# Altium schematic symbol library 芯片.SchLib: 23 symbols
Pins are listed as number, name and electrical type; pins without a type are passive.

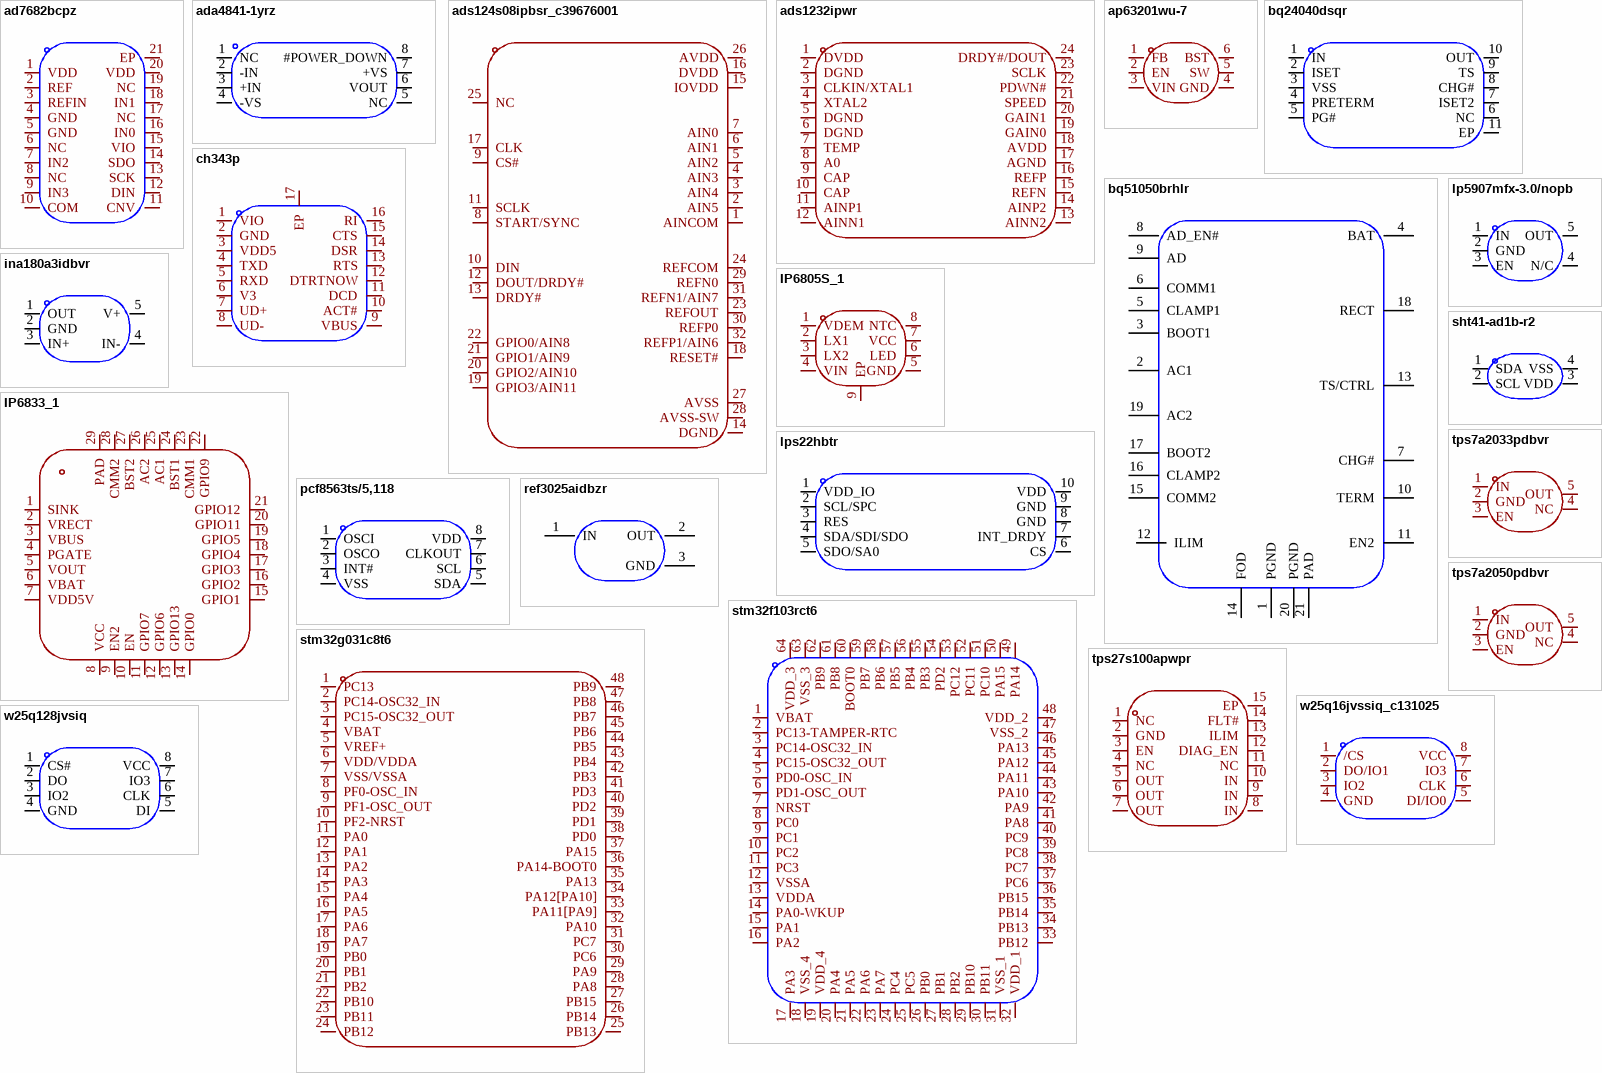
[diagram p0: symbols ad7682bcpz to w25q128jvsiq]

## ad7682bcpz
designator U??  (value not drawn)
分辨率(位):16;采样率:250kHz;工作电压:2.3V~5.5V;接口类型:SPI;; Manufacturer: ADI(亚德诺); AddInBom: yes; ModelId: a3340110063d416e8a07a046bfa25306; ModelName: LFCSP-20_L4.0-W4.0-H1.0-P0.50; ModelTransform: 157.48,157.48,0,90,0,0,-0.003,0.003,0; Resolution (Bits): 16; Sampling Rate: 250kHz; number of channels: 4; Interface: SPI; differential input: 是; Integral non - linearity: 0.4LSB; Signal-to-Noise Ratio: 92.5dB; Clock/Oscillator: 内置; ADC architecture: SAR; Quiescent Current (Iq): 50nA; DNL (LSB): 0.25LSB
footprint LFCSP-20_L4.0-W4.0-P0.50-BL-EP
pins: 1 VDD, 2 REF, 3 REFIN, 4 GND, 5 GND, 6 NC, 7 IN2, 8 NC, 9 IN3, 10 COM, 11 CNV, 12 DIN, 13 SCK, 14 SDO, 15 VIO, 16 IN0, 17 NC, 18 IN1, 19 NC, 20 VDD, 21 EP

## ada4841-1yrz
designator U??  (value not drawn)
放大器数:1;轨到轨:轨到轨输出;增益带宽积(GBW):80MHz;输入失调电压(Vos):300uV;压摆率(SR):12V/us;输入偏置电流(Ib):5.3uA;; Manufacturer: ADI(亚德诺); AddInBom: yes; ModelId: 7abc64c95a1a4a04a4ef38f9097c870b; ModelName: SOIC-8_L5.0-W4.0-P1.27-LS6.0-BL; ModelTransform: 192.913,236.22,0,0,0,0,0,0,0; Number of Channels: 1; Rail to Rail: 轨到轨输出; Gain Bandwidth Product: 80MHz; Vos - Input Offset Voltage: 300uV; Input Offset Voltage Drift(Vos TC): 1uV/℃; Slew Rate: 12V/us; Ib - Input Bias Current: 5.3uA; Input Offset Current(Ios): 500nA; Input Voltage Noise Density: 2.1nV/√Hz@100kHz; Common Mode Rejection Ratio(CMRR): 115dB; Quiescent Current: 1.5mA; Output Current: 30mA; Single supply: 2.7V~12V
footprint SOIC-8_L5.0-W4.0-P1.27-LS6.0-BL
pins: 1 NC, 2 -IN, 3 +IN, 4 -VS, 5 NC, 6 VOUT, 7 +VS, 8 #POWER_DOWN

## ads124s08ipbsr_c39676001
designator U??  (value not drawn)
分辨率(位):24;采样率:4kHz;工作电压:2.7V~5.25V;接口类型:SPI;; Manufacturer: TI(德州仪器); AddInBom: yes; ModelId: 0723864a05e7424ab80b3c78d6a7d93a; ModelName: TQFP-32_L5.0-W5.0-H1.2-LS7.0-P0.50; ModelTransform: 277.58783,277.58783,0,90,0,0,0.013,0,0; Resolution (Bits): 24; Sampling Rate: 4kHz; number of channels: 12; Interface: SPI; differential input: 是; Clock/Oscillator: 内置; Clock Frequency: 4.096MHz; Programmable Gain: 支持; Quiescent Current (Iq): 280uA
footprint TQFP-32_L5.0-W5.0-P0.50-LS7.0-BL
pins: 1 AINCOM, 2 AIN5, 3 AIN4, 4 AIN3, 5 AIN2, 6 AIN1, 7 AIN0, 8 START/SYNC, 9 CS#, 10 DIN, 11 SCLK, 12 DOUT/DRDY#, 13 DRDY#, 14 DGND, 15 IOVDD, 16 DVDD, 17 CLK, 18 RESET#, 19 GPIO3/AIN11, 20 GPIO2/AIN10, 21 GPIO1/AIN9, 22 GPIO0/AIN8, 23 REFOUT, 24 REFCOM, 25 NC, 26 AVDD, 27 AVSS, 28 AVSS-SW, 29 REFN0, 30 REFP0, 31 REFN1/AIN7, 32 REFP1/AIN6

## ads1232ipwr
designator U??  (value not drawn)
分辨率(位):24;采样率:10Hz;工作电压:2.7V~5.3V;接口类型:SPI;; Manufacturer: TI(德州仪器); AddInBom: yes; ModelId: 57e278220af748a2882c4abba4094eb9; ModelName: TSSOP-24_L7.8-W4.4-H1.0-LS6.4-P0.65; ModelTransform: 252.188,307.086,0,90,0,0,0,0,0; Resolution (Bits): 24; Sampling Rate: 10Hz; number of channels: 2; Interface: SPI; differential input: 是; Clock/Oscillator: 内置；外置; Clock Frequency: 4.9152MHz；200kHz~8MHz; Voltage Reference: 外置; Programmable Gain: 支持; Temperature Sensors: 内置; ADC architecture: Sigma-Delta; Data rate: 80Hz；10Hz; Quiescent Current (Iq): 1.3uA; Full-Scale Range(FSR): 39mV；1.25V；19.5mV；2.5V
footprint TSSOP-24_L7.8-W4.4-P0.65-LS6.4-BL
footprint Model Name (Footprint not found)
pins: 1 DVDD, 2 DGND, 3 CLKIN/XTAL1, 4 XTAL2, 5 DGND, 6 DGND, 7 TEMP, 8 A0, 9 CAP, 10 CAP, 11 AINP1, 12 AINN1, 13 AINN2, 14 AINP2, 15 REFN, 16 REFP, 17 AGND, 18 AVDD, 19 GAIN0, 20 GAIN1, 21 SPEED, 22 PDWN#, 23 SCLK, 24 DRDY#/DOUT

## ap63201wu-7
designator U??  (value not drawn)
功能类型:降压型;工作电压:3.8V~32V;输出电压:-;输出电流:2A;输出类型:可调;; Manufacturer: DIODES(美台); AddInBom: yes; ModelId: 2c4039b5b88644c1bda4b4ba9e971667; ModelName: TSOT-23-6_L2.9-W1.6-H1.1-LS2.8-P0.95; ModelTransform: 110.45568,114.173,0,180,0,0,-0.005,-0.0005,0; Function: 降压型; Output Current: 2A; Frequency - Switching: 500kHz; Synchronous Rectifier: 是; Number of Outputs: 1; Topology: 降压式; Quiescent Current: 22uA; Switch tube (built-in/external): 内置; Output Type: 可调
footprint TSOT-23-6_L2.9-W1.6-P0.95-LS2.8-BR
pins: 1 FB, 2 EN, 3 VIN, 4 GND, 5 SW, 6 BST

## bq24040dsqr
designator U??  (value not drawn)
工作电压:3.5V~28V;最大充电电流:1A;电池类型:锂电池;电池节数:1;; Manufacturer: TI(德州仪器); AddInBom: yes; ModelId: 0e1275d2e7d54e69a402a354e9203fe9; ModelName: WSON-10_L2.0-W2.0-H0.8-P0.40; ModelTransform: 78.74,79.527,0,0,0,0,0,0,0; The Chip Type: 充电芯片; Charge Current - Max: 1A; Charging Saturation Voltage: 4.2V; End-Off Voltage: 800mV; Type of Battery: 锂电池; Number of Cells: 1; Battery Temperature Detection: 支持; Supply Current (Iq): 1mA
footprint WSON-10_L2.0-W2.0-P0.40-BL-EP
pins: 1 IN, 2 ISET, 3 VSS, 4 PRETERM, 5 PG#, 6 NC, 7 ISET2, 8 CHG#, 9 TS, 10 OUT, 11 EP

## bq51050brhlr
designator U??  (value not drawn)
工作电压:4V~10V;最大充电电流:1.5A;电池类型:锂电池;电池节数:-;; Manufacturer: TI(德州仪器); AddInBom: yes; ModelId: 106b197ca8ab4e02bb62e74add4294be; ModelName: QFN-20_L4.5-W3.5-H1.0-P0.50; ModelTransform: 177.952,138.5824,0,0,0,0,0,0,0; The Chip Type: 充电芯片; Voltage - Supply: 4V~10V; Charge Current - Max: 1.5A; Charging Saturation Voltage: 4.2V; Type of Battery: 锂电池; Battery Temperature Detection: 支持; Supply Current (Iq): 3uA
footprint QFN-20_L4.7-W3.7-P0.50-BL-EP
pins: 1 PGND, 2 AC1, 3 BOOT1, 4 BAT, 5 CLAMP1, 6 COMM1, 7 CHG#, 8 AD_EN#, 9 AD, 10 TERM, 11 EN2, 12 ILIM, 13 TS/CTRL, 14 FOD, 15 COMM2, 16 CLAMP2, 17 BOOT2, 18 RECT, 19 AC2, 20 PGND, 21 PAD

## ch343p
designator U??  (value not drawn)
应用功能:USB转UART;USB协议版本:USB 2.0;通道数:-;数据速率:6Mbps;; Manufacturer: WCH(南京沁恒); AddInBom: yes; ModelId: bf3177fc8dab4136825cc9ae9b354cf2; ModelName: TQFN-16_L3.0-W3.0-P0.50-BL-EP1.7; ModelTransform: 118.8974,118.8974,0,0,0,0,0,0,0; USB Protocol: USB 2.0; Voltage - Supply: 3.3V；5V; Data Rate: 6Mbps; Current - Supply: 3mA; Quiescent Supply Current: 90uA
footprint TQFN-16_L3.0-W3.0-P0.50-BL-EP1.7
pins: 1 VIO, 2 GND, 3 VDD5, 4 TXD, 5 RXD, 6 V3, 7 UD+, 8 UD-, 9 VBUS, 10 ACT#, 11 DCD, 12 DTRTNOW, 13 RTS, 14 DSR, 15 CTS, 16 RI, 17 EP

## ina180a3idbvr
designator U??  (value not drawn)
放大器数:1;共模电压:-200mV~26V;增益:100V/V;带宽(-3db):150kHz;; Manufacturer: TI(德州仪器); AddInBom: yes; ModelId: 0a2a1b8f50944f73965918ad6e5fe167; ModelName: SOT-23-5_L2.9-W1.6-H1.1-LS2.8-P0.95; ModelTransform: 114.173,109.636,0,180,0,0,0,0,0; Number of Channels: 1; Gain: 100V/V; Bandwidth: 150kHz; Ib - Input Bias Current: 100nA; Vos - Input Offset Voltage: 25uV; Differential Voltage: ±26V; Single Supply: 2.7V~5.5V; Quiescent Current: 197uA; Output Current: 8mA; Input Offset Voltage Drift(Vos TC): 1uV/℃; Slew Rate: 2V/us; Common Mode Rejection Ratio (CMRR): 100dB; Noise density(eN): 40nV/√Hz@1kHz
footprint SOT-23-5_L3.0-W1.7-P0.95-LS2.8-BR
pins: 1 OUT, 2 GND, 3 IN+, 4 IN-, 5 V+

## IP6805S_1
designator U??  (value not drawn)
footprint ESOP-8_L4.9-W3.9-P1.27-LS6.0-BL-EP3.1
pins: 1 VDEM, 2 LX1, 3 LX2, 4 VIN, 5 GND, 6 LED, 7 VCC, 8 NTC, 9 EP

## IP6833_1
designator U??  (value not drawn)
footprint IP6833
pins: 1 SINK, 2 VRECT, 3 VBUS, 4 PGATE, 5 VOUT, 6 VBAT, 7 VDD5V, 8 VCC, 9 EN2, 10 EN, 11 GPIO7, 12 GPIO6, 13 GPIO13, 14 GPIO0, 15 GPIO1, 16 GPIO2, 17 GPIO3, 18 GPIO4, 19 GPIO5, 20 GPIO11, 21 GPIO12, 22 GPIO9, 23 CMM1, 24 BST1, 25 AC1, 26 AC2, 27 BST2, 28 CMM2, 29 PAD

## lp5907mfx-3.0/nopb
designator U??  (value not drawn)
输出极性:正极;工作电压:5.5V;输出电压:3V;输出电流:250mA;电源纹波抑制比(PSRR):82dB@(1kHz);输出类型:固定;; Manufacturer: TI(德州仪器); AddInBom: yes; ModelId: 0a2a1b8f50944f73965918ad6e5fe167; ModelName: SOT-23-5_L2.9-W1.6-H1.1-LS2.8-P0.95; ModelTransform: 118.60433,114.173,0,90,0,0,0.0005,0.0005,0; Output Configuration: 正极; Voltage - Supply: 5.5V; Output Voltage: 3V; Output Current: 250mA; Voltage Dropout: 120mV@(250mA); standby current: 12uA; Noise: 6.5uVrms; Output Type: 固定; Number of Outputs: 1
footprint SOT-23-5_L3.0-W1.7-P0.95-LS2.8-BL
pins: 1 IN, 2 GND, 3 EN, 4 N/C, 5 OUT

## lps22hbtr
designator U??  (value not drawn)
压力范围:26Kpa~1.26bar;接口类型:SPI；I2C;; Manufacturer: ST(意法半导体); AddInBom: yes; ModelId: d5ee430d14324ccb82effb2dc42ae2a1; ModelName: HLGA-10L_L2.0-W2.0-H0.8-P0.5-LPS22HBTR; ModelTransform: 78.74,78.74,0,0,0,0,0,0.195,0; Voltage - Supply: 1.7V~3.6V; Standby Current: 1uA; Module: 否; Absolute Accuracy: 0.1hpa
footprint HLGA-10L_LPS22HBTR
pins: 1 VDD_IO, 2 SCL/SPC, 3 RES, 4 SDA/SDI/SDO, 5 SDO/SA0, 6 CS, 7 INT_DRDY, 8 GND, 9 GND, 10 VDD

## pcf8563ts/5,118
designator U??  (value not drawn)
接口类型:I2C;晶振类型:外置;闹钟输出:有;; Manufacturer: NXP(恩智浦); AddInBom: yes; ModelId: 6d0b9b814610470cb34a1acf75d8754c; ModelName: TSSOP-8_L3.0-W3.0-H1.1-LS4.9-P0.65; ModelTransform: 118.11,192.913,0,0,0,0,0,-0.0005,0; Interface: I2C; crystal oscillator: 外置; Alarm Output: 有; Current - Supply: 250nA; Voltage - Supply: 1.8V~5.5V; Quiescent Current(Iq): 0.25uA
footprint TSSOP-8_L3.0-W3.0-P0.65-LS4.9-BL
pins: 1 OSCI, 2 OSCO, 3 INT#, 4 VSS, 5 SDA, 6 SCL, 7 CLKOUT, 8 VDD

## ref3025aidbzr
designator U??  (value not drawn)
输出类型:固定;工作电压:2.55V~5.5V;输出电压:2.5V;输出电流:25mA;精度:±0.2%;; Manufacturer: TI(德州仪器); AddInBom: yes; ModelId: 89cb27a44ab2466697082bb9fd73a7d0; ModelName: SOT-23-3L_L2.9-W1.6-H1.1-LS2.8-P0.95; ModelTransform: 114.173,110.236,0,90,0,0,0,0,0; Output Type: 固定; Output Voltage: 2.5V; Output Current: 25mA; Tolerance: ±0.2%; Temperature Coefficient: 75ppm/℃; Reference Type: 串联; Quiescent Current: 50uA; Noise - 1/10Hz to 10Hz: 28uVp-p; Noise - 10Hz to 10kHz: 80uVrms
footprint SOT-23-3_L2.9-W1.6-P1.90-LS2.8-BR
pins: 1 IN, 2 OUT, 3 GND

## sht41-ad1b-r2
designator U??  (value not drawn)
温度范围:-40℃~+125℃;湿度范围:0%RH~100%RH;接口类型:I2C;湿度精度:±1.8%RH;; Manufacturer: Sensirion(瑞士盛思锐); AddInBom: yes; ModelId: d740bd0688d14669b1c87f9602af067d; ModelName: DFN-4_L1.5-W1.5-SHT41-AD1B-R2; ModelTransform: 59.13374,59.055,0,0,0,0,0,0,0; Interface: I2C; Voltage - Supply: 1.08V~3.6V; Current - Supply: 400nA; Humidity Tolerance: ±1.8%RH; Temperature Tolerance: ±0.2℃; Resolution: 16bit
footprint DFN-4_L1.5-W1.5-SHT41-AD1B-R2
pins: 1 SDA, 2 SCL, 3 VDD, 4 VSS

## stm32f103rct6
designator U??  (value not drawn)
CPU内核:ARM Cortex-M3;CPU最大主频:72MHz;CPU位数:32 Bit;; Manufacturer: ST(意法半导体); AddInBom: yes; ModelId: cd9de06618c44fcf82654c43a457f83c; ModelName: LQFP-64_L10.0-W10.0-H1.4-LS12.0-P0.50; ModelTransform: 472.441,472.441,0,0,0,0,0,0.465,0; CPU Maximum Speed: 72MHz; Core Size: 32 Bit; Program Storage Size: 256KB; Program Memory Type: FLASH; RAM Size: 48KB; Number of I/O: 51; ADC (Bit): 12bit; Oscillator Type: 内置; Voltage - Supply: 2V~3.6V
footprint LQFP-64_L10.0-W10.0-P0.50-LS12.0-BL
pins: 1 VBAT, 2 PC13-TAMPER-RTC, 3 PC14-OSC32_IN, 4 PC15-OSC32_OUT, 5 PD0-OSC_IN, 6 PD1-OSC_OUT, 7 NRST, 8 PC0, 9 PC1, 10 PC2, 11 PC3, 12 VSSA, 13 VDDA, 14 PA0-WKUP, 15 PA1, 16 PA2, 17 PA3, 18 VSS_4, 19 VDD_4, 20 PA4, 21 PA5, 22 PA6, 23 PA7, 24 PC4, 25 PC5, 26 PB0, 27 PB1, 28 PB2, 29 PB10, 30 PB11, 31 VSS_1, 32 VDD_1, 33 PB12, 34 PB13, 35 PB14, 36 PB15, 37 PC6, 38 PC7, 39 PC8, 40 PC9, 41 PA8, 42 PA9, 43 PA10, 44 PA11, 45 PA12, 46 PA13, 47 VSS_2, 48 VDD_2, 49 PA14, 50 PA15, 51 PC10, 52 PC11, 53 PC12, 54 PD2, 55 PB3, 56 PB4, 57 PB5, 58 PB6, 59 PB7, 60 BOOT0, 61 PB8, 62 PB9, 63 VSS_3, 64 VDD_3

## stm32g031c8t6
designator U??  (value not drawn)
CPU内核:ARM Cortex-M0+;CPU最大主频:64MHz;CPU位数:32 Bit;; Manufacturer: ST(意法半导体); AddInBom: yes; ModelId: 093be70396ff421eb2cdb946d5311efc; ModelName: LQFP-48_L7.0-W7.0-H1.4-LS9.0-P0.50; ModelTransform: 354.331,354.331,0,0,0,0,0,0,0; CPU Maximum Speed: 64MHz; Core Size: 32 Bit; Program Storage Size: 64KB; Program Memory Type: FLASH; RAM Size: 8KB; Number of I/O: 44; ADC (Bit): 12bit; Oscillator Type: 内置+外置; Voltage - Supply: 1.7V~3.6V
footprint LQFP-48_L7.0-W7.0-P0.50-LS9.0-BL
pins: 1 PC13, 2 PC14-OSC32_IN, 3 PC15-OSC32_OUT, 4 VBAT, 5 VREF+, 6 VDD/VDDA, 7 VSS/VSSA, 8 PF0-OSC_IN, 9 PF1-OSC_OUT, 10 PF2-NRST, 11 PA0, 12 PA1, 13 PA2, 14 PA3, 15 PA4, 16 PA5, 17 PA6, 18 PA7, 19 PB0, 20 PB1, 21 PB2, 22 PB10, 23 PB11, 24 PB12, 25 PB13, 26 PB14, 27 PB15, 28 PA8, 29 PA9, 30 PC6, 31 PC7, 32 PA10, 33 PA11[PA9], 34 PA12[PA10], 35 PA13, 36 PA14-BOOT0, 37 PA15, 38 PD0, 39 PD1, 40 PD2, 41 PD3, 42 PB3, 43 PB4, 44 PB5, 45 PB6, 46 PB7, 47 PB8, 48 PB9

## tps7a2033pdbvr
designator U??  (value not drawn)
输出类型:固定;最大输入电压:6V;输出电压:3.3V;输出电流:300mA;输出极性:正极;; Manufacturer: TI(德州仪器); AddInBom: yes; ModelId: 7ba65df16e7b4570af156e925f9c37fe; ModelName: SOT-23-5_L2.9-W1.6-P0.95-LS2.8-BR; ModelTransform: 114.173,114.173,0,90,0,0,0,0,0; Output Type: 固定; Maximum Input Voltage: 6V; Output Voltage: 3.3V; Output Current: 300mA; Dropout Voltage: 140mV@(300mA); standby current: 15uA; Output Polarity: 正极; Number of Outputs: 1
footprint SOT-23-5_L2.9-W1.6-P0.95-LS2.8-BR
pins: 1 IN, 2 GND, 3 EN, 4 NC, 5 OUT

## tps7a2050pdbvr
designator U??  (value not drawn)
输出极性:正极;工作电压:6V;输出电压:5V;输出电流:300mA;电源纹波抑制比(PSRR):65dB@(100Hz);输出类型:固定;; Manufacturer: TI(德州仪器); AddInBom: yes; ModelId: 7ba65df16e7b4570af156e925f9c37fe; ModelName: SOT-23-5_L2.9-W1.6-P0.95-LS2.8-BR; ModelTransform: 114.173,114.173,0,90,0,0,0,0,0; Output Configuration: 正极; Voltage - Supply: 6V; Output Voltage: 5V; Output Current: 300mA; Voltage Dropout: 140mV@(300mA); standby current: 6.5uA; Noise: 10uVrms; Output Type: 固定; Number of Outputs: 1
footprint SOT-23-5_L2.9-W1.6-P0.95-LS2.8-BR
pins: 1 IN, 2 GND, 3 EN, 4 NC, 5 OUT

## tps27s100apwpr
designator U??  (value not drawn)
类型:高侧开关;通道数:1;输入控制逻辑:高电平有效;工作电压:3.5V~40V;最大连续电流:4A;导通电阻:80mΩ;; Manufacturer: TI(德州仪器); AddInBom: yes; ModelId: 02f1f60386074b2ca8e111040ac061f2; ModelName: TSSOP-14_L5.0-W4.4-H1.0-LS6.4-P0.65; ModelTransform: 236.714,196.85,0,90,0,0,0,0.0005,0; Number of Channels: 1; Control Input Logic: 高电平有效; Maximum Continuous Current: 4A; RDS(on): 80mΩ
footprint TSSOP-14_L5.0-W4.4-P0.65-LS6.4-BL-EP
pins: 1 NC, 2 GND, 3 EN, 4 NC, 5 OUT, 6 OUT, 7 OUT, 8 IN, 9 IN, 10 IN, 11 NC, 12 DIAG_EN, 13 ILIM, 14 FLT#, 15 EP

## w25q16jvssiq_c131025
designator U??  (value not drawn)
接口类型:SPI;存储容量:16Mbit;时钟频率(fc):133MHz;; Manufacturer: Winbond(华邦); Symbol: W25Q16JVSSIQTR; AddInBom: yes; ModelId: f83d990ad74f400caf5ac920b7771508; ModelName: SOIC-8_L5.3-W5.3-H1.9-LS7.9-P1.27; ModelTransform: 208.661,311.25654,0,0,0,0,-0.0005,0.0005,0; Interface: SPI; Memory Size: 16Mbit; Clock Frequency: 133MHz; Voltage - Supply: 2.7V~3.6V; Standby Supply Current: 10uA; Program / Erase Cycles: 100000次; Page Programming Time (Tpp): 3ms; Data Retention - TDR (Year): 20年
footprint SOIC-8_L5.3-W5.3-P1.27-LS8.0-BL
pins: 1 /CS, 2 DO/IO1, 3 IO2, 4 GND, 5 DI/IO0, 6 CLK, 7 IO3, 8 VCC

## w25q128jvsiq
designator U??  (value not drawn)
接口类型:SPI;存储容量:128Mbit;时钟频率(fc):133MHz;; Manufacturer: Winbond(华邦); Symbol: W25Q128JVSIQTR; AddInBom: yes; ModelId: f83d990ad74f400caf5ac920b7771508; ModelName: SOIC-8_L5.3-W5.3-H1.9-LS7.9-P1.27; ModelTransform: 208.661,311.25654,0,0,0,0,-0.0005,0.0005,0; Interface: SPI; Clock Frequency: 133MHz; Voltage - Supply: 2.7V~3.6V; Standby Supply Current: 1uA; Program / Erase Cycles: 100000次; Page Programming Time (Tpp): 3ms; Block Erase Time(tBE): 120ms@(32KB); Data Retention - TDR (Year): 20年
footprint SOIC-8_L5.3-W5.3-P1.27-LS8.0-BL
pins: 1 CS#, 2 DO, 3 IO2, 4 GND, 5 DI, 6 CLK, 7 IO3, 8 VCC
